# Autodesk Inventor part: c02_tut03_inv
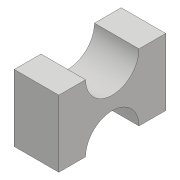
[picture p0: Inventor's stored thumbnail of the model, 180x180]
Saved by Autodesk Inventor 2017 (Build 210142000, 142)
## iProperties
Created: 2016-07
Part Number: c02_tut03_inv
Material: Generic
Document SubType Name: Modeling
Designer: Sandeep
Density: 1 g/cm^3
Appearance: Default
Author: Sandeep
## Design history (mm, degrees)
sketch "Sketch1"
  geometry: L1 (-24, 30)-(-12, 30); L2 (12, 30)-(24, 30); L3 (24, 30)-(24, 0); L4 (24, 0)-(12, 0); L5 (-12, 0)-(-24, 0); L6 (-24, 0)-(-24, 30); L7 (0, 0)-(0, 32.308); A1 r 12 centre (0, 30) between (-12, 30) and (12, 30); A2 r 12 centre (0, 0) between (12, 0) and (-12, 0)
  constraints: 14 end point, 6 point on line, 4 point on circle, 3 perpendicular, 2 centre point, 1 equal radius, 1 horizontal, 1 vertical, 1 other
  dimensions: "d0" = 30 distance between parallel lines of L4 L2; "d1" = 48 distance between parallel lines of L6 L3; "d2" = 12 radius of A1
extrude "Extrusion1" new body sketch "Sketch1" distance "d3" = 20; taper "d4" = 0 deg
body "Solid1"
